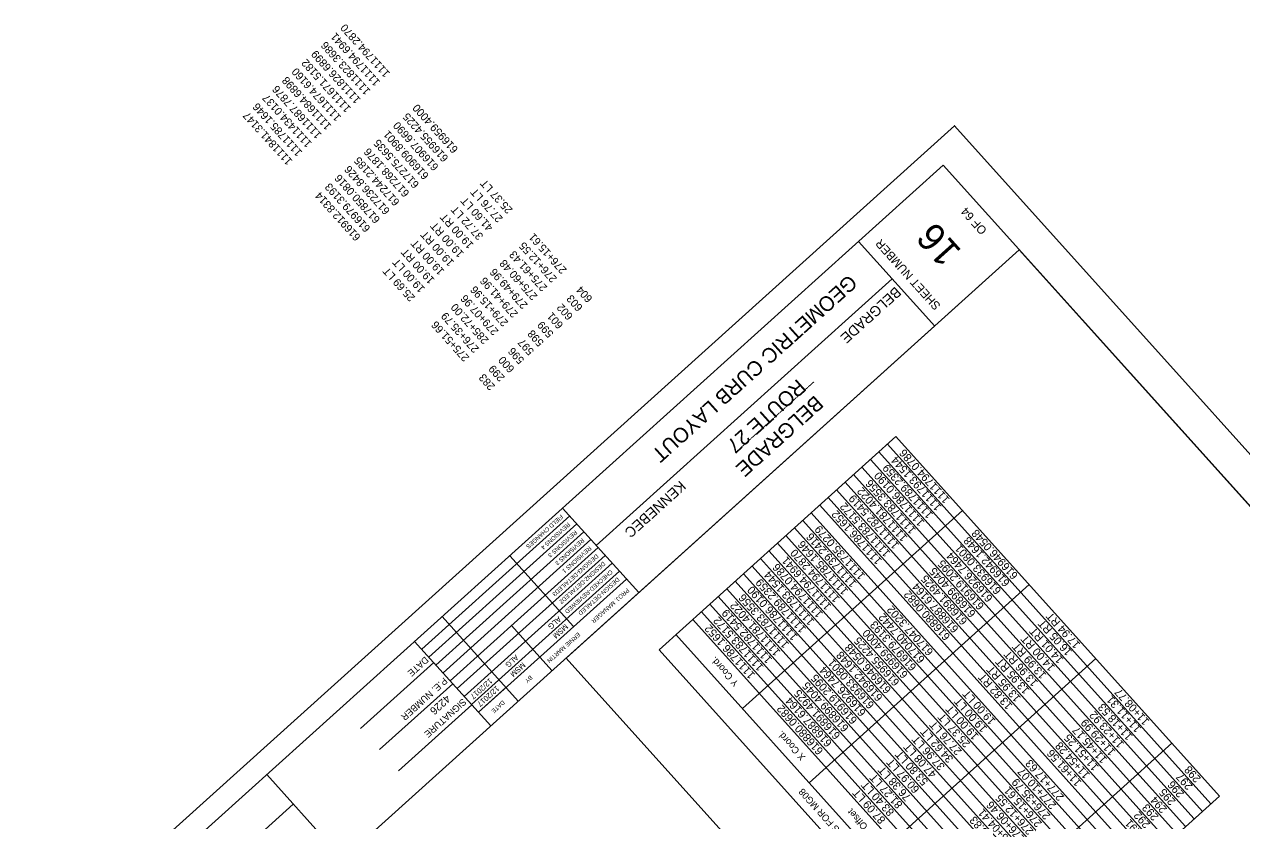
# Model space of a CAD drawing. Extents: x 1111534 to 1112511, y 616515 to 617559.
# Drawn here: x 1111534 to 1112068, y 617209 to 617559 of the extents above; entities that cross this region are included whole.
import ezdxf

# ---------------------------------------------------------------- set-up
doc = ezdxf.new("R2010")
doc.units = 0
for name, color, linetype in [('ANNOTATION', 7, 'Continuous'), ('BORDER', 7, 'Continuous'), ('BRIDGE_TITLE', 7, 'Continuous'), ('CLIPS', 7, 'Continuous'), ('H_V CONTROLS', 7, 'Continuous'), ('HIGHWAY_TITLE', 7, 'Continuous'), ('PLOT BOUNDARY', 7, 'Continuous')]:
    doc.layers.add(name, color=color, linetype=linetype)

msp = doc.modelspace()

# ---------------------------------------------------------------- linework, layer by layer
at = {"layer": 'BORDER'}
for p, q in [((1111937.23, 617496.95), (1111547.08, 617145.66)), ((1112472.55, 616902.44), (1111937.25, 617496.96)), ((1111970.69, 617459.79), (1111580.54, 617108.5)), ((1111933.53, 617426.34), (1111900.08, 617463.49)), ((1111914.83, 617447.11), (1111784.78, 617330.01)), ((1111803.48, 617309.24), (1111770.03, 617346.39)), ((1111738.46, 617250.69), (1111705, 617287.85)), ((1111713.37, 617278.56), (1111681.23, 617249.63)), ((1111721.73, 617269.27), (1111689.6, 617240.34)), ((1111730.09, 617259.98), (1111697.96, 617231.05)), ((1111673.46, 617192.17), (1111640.01, 617229.33)), ((1111651.63, 617216.4), (1111558.74, 617132.76))]:
    msp.add_line(p, q, dxfattribs=at)
for points in [[(1111773.13, 617342.93), (1111708.12, 617284.39)], [(1111776.25, 617339.46), (1111711.23, 617280.93)], [(1111779.36, 617336), (1111714.35, 617277.46)], [(1111782.48, 617332.54), (1111717.47, 617274)], [(1111785.6, 617329.08), (1111720.58, 617270.54)], [(1111788.72, 617325.62), (1111723.7, 617267.08)], [(1111726.82, 617263.62), (1111791.83, 617322.16)], [(1111774.86, 617294.33), (1111746.8, 617325.48)], [(1111794.95, 617318.69), (1111729.94, 617260.15)], [(1111798.07, 617315.23), (1111735.68, 617259.05)], [(1111750.53, 617261.56), (1111717.08, 617298.72)], [(1111759.99, 617280.95), (1111747.53, 617294.79)], [(1111765.4, 617274.94), (1111759.99, 617280.95)], [(1111745.13, 617267.56), (1111733.06, 617256.69)]]:
    msp.add_lwpolyline(points, dxfattribs=at)
at = {"layer": 'CLIPS'}
msp.add_lwpolyline([(1112472.55, 616902.44), (1111970.7, 617459.8), (1111771.54, 617280.48), (1112273.39, 616723.12)], close=True, dxfattribs=at)
at = {"layer": 'H_V CONTROLS'}
for p, q in [((1111812.4, 617284.13), (1111916.44, 617377.81)), ((1112054.91, 617216.54), (1111912.72, 617374.46)), ((1112058.63, 617219.89), (1111916.44, 617377.81)), ((1112051.2, 617213.2), (1111909.01, 617371.11)), ((1112043.76, 617206.51), (1111901.57, 617364.42)), ((1112047.48, 617209.85), (1111905.29, 617367.77)), ((1112036.33, 617199.81), (1111894.14, 617357.73)), ((1112040.05, 617203.16), (1111897.86, 617361.08)), ((1112032.62, 617196.47), (1111890.43, 617354.39)), ((1112025.19, 617189.78), (1111883, 617347.7)), ((1112028.9, 617193.12), (1111886.71, 617351.04)), ((1111849.1, 617258.31), (1111945.71, 617345.29)), ((1112021.47, 617186.43), (1111879.28, 617344.35)), ((1112014.04, 617179.74), (1111871.85, 617337.66)), ((1112017.75, 617183.09), (1111875.56, 617341)), ((1112010.32, 617176.39), (1111868.13, 617334.31)), ((1112002.89, 617169.7), (1111860.7, 617327.62)), ((1112006.61, 617173.05), (1111864.42, 617330.97)), ((1111995.46, 617163.01), (1111853.27, 617320.93)), ((1111999.18, 617166.36), (1111856.99, 617324.28)), ((1111991.74, 617159.67), (1111849.55, 617317.58)), ((1111984.31, 617152.97), (1111842.12, 617310.89)), ((1111988.03, 617156.32), (1111845.84, 617314.24)), ((1111878.38, 617225.79), (1111974.99, 617312.78)), ((1111980.6, 617149.63), (1111838.41, 617307.55)), ((1111973.17, 617142.94), (1111830.98, 617300.86)), ((1111976.88, 617146.28), (1111834.69, 617304.2)), ((1111969.45, 617139.59), (1111827.26, 617297.51)), ((1111962.02, 617132.9), (1111819.83, 617290.82)), ((1111954.59, 617126.21), (1111812.4, 617284.13)), ((1111907.65, 617193.28), (1112004.26, 617280.27)), ((1111941.11, 617156.12), (1112037.72, 617243.11)), ((1111954.59, 617126.21), (1112058.63, 617219.89))]:
    msp.add_line(p, q, dxfattribs=at)
at = {"layer": 'PLOT BOUNDARY'}
msp.add_lwpolyline([(1112510.99, 616882.61), (1111942.23, 617514.28), (1111533.5, 617146.26), (1112102.26, 616514.59)], close=True, dxfattribs=at)

# ---------------------------------------------------------------- texts
at = {"layer": 'ANNOTATION'}
for s, height, rotation, p in [('1111794.2870', 3.45, 132, (1111694.36, 617537.42)), ('1111823.3686', 3.45, 132, (1111685.8, 617529.71)), ('1111794.6941', 3.45, 132, (1111690.08, 617533.57)), ('1111826.6899', 3.45, 132, (1111681.52, 617525.86)), ('1111671.5182', 3.45, 132, (1111677.24, 617522)), ('1111684.6898', 3.45, 132, (1111668.68, 617514.29)), ('1111674.6160', 3.45, 132, (1111672.96, 617518.14)), ('1111687.7876', 3.45, 132, (1111664.39, 617510.43)), ('1111785.1646', 3.45, 132, (1111655.83, 617502.72)), ('1111434.0137', 3.45, 132, (1111660.11, 617506.58)), ('616959.4000', 3.45, 132, (1111724.35, 617504.12)), ('1111841.3147', 3.45, 132, (1111651.55, 617498.87)), ('616955.4225', 3.45, 132, (1111720.07, 617500.26)), ('616907.6690', 3.45, 132, (1111715.79, 617496.41)), ('617275.5635', 3.45, 132, (1111707.22, 617488.7)), ('616909.8901', 3.45, 132, (1111711.5, 617492.55)), ('617268.1876', 3.45, 132, (1111702.94, 617484.84)), ('617244.2185', 3.45, 132, (1111698.66, 617480.99)), ('617850.0816', 3.45, 132, (1111690.1, 617473.28)), ('617236.8426', 3.45, 132, (1111694.38, 617477.13)), ('616979.3193', 3.45, 132, (1111685.81, 617469.42)), ('27.76 LT', 3.45, 132, (1111744, 617473.69)), ('25.37 LT', 3.45, 132, (1111748.28, 617477.54)), ('616912.8314', 3.45, 132, (1111681.53, 617465.57)), ('41.60 LT', 3.45, 132, (1111739.71, 617469.83)), ('37.72 LT', 3.45, 132, (1111735.43, 617465.98)), ('19.00 RT', 3.45, 132, (1111726.87, 617458.27)), ('19.00 RT', 3.45, 132, (1111731.15, 617462.12)), ('19.00 RT', 3.45, 132, (1111722.59, 617454.41)), ('276+15.61', 3.45, 132, (1111772.06, 617451.13)), ('19.00 RT', 3.45, 132, (1111714.02, 617446.7)), ('19.00 RT', 3.45, 132, (1111718.31, 617450.56)), ('276+12.55', 3.45, 132, (1111767.78, 617447.28)), ('19.00 LT', 3.45, 132, (1111709.74, 617442.85)), ('275+60.48', 3.45, 132, (1111759.21, 617439.57)), ('275+61.43', 3.45, 132, (1111763.5, 617443.42)), ('25.69 LT', 3.45, 132, (1111705.46, 617438.99)), ('279+49.96', 3.45, 132, (1111754.93, 617435.71)), ('279+15.96', 3.45, 132, (1111746.37, 617428)), ('279+41.96', 3.45, 132, (1111750.65, 617431.86)), ('604', 3.45, 132, (1111783.41, 617438.53)), ('279+07.96', 3.45, 132, (1111742.09, 617424.15)), ('603', 3.45, 132, (1111779.13, 617434.67)), ('285+72.00', 3.45, 132, (1111737.81, 617420.29)), ('602', 3.45, 132, (1111774.84, 617430.82)), ('275+51.66', 3.45, 132, (1111729.24, 617412.58)), ('276+35.79', 3.45, 132, (1111733.52, 617416.44)), ('599', 3.45, 132, (1111766.28, 617423.11)), ('601', 3.45, 132, (1111770.56, 617426.96)), ('598', 3.45, 132, (1111762, 617419.25)), ('596', 3.45, 132, (1111753.44, 617411.54)), ('597', 3.45, 132, (1111757.72, 617415.4)), ('600', 3.45, 132, (1111749.15, 617407.69)), ('299', 3.45, 132, (1111744.87, 617403.83)), ('283', 3.45, 132, (1111740.59, 617399.98)), ('1111793.1544', 3.5156, 132, (1111936.79, 617347.07)), ('1111794.0786', 3.5156, 132, (1111940.37, 617350.29)), ('1111789.2359', 3.5156, 132, (1111933.02, 617343.68)), ('1111783.3556', 3.5156, 132, (1111925.49, 617336.89)), ('1111786.0190', 3.5156, 132, (1111929.27, 617340.3)), ('1111781.4022', 3.5156, 132, (1111921.8, 617333.57)), ('1111783.5172', 3.5156, 132, (1111914.27, 617326.79)), ('1111782.5419', 3.5156, 132, (1111918.13, 617330.27)), ('1111786.1652', 3.5156, 132, (1111910.58, 617323.47)), ('1111735.0279', 3.5156, 132, (1111903.15, 617316.78)), ('616946.0548', 3.5156, 132, (1111970.37, 617316.97)), ('1111785.1646', 3.5156, 132, (1111895.75, 617310.11)), ('1111739.2416', 3.5156, 132, (1111899.47, 617313.46)), ('616942.1648', 3.5156, 132, (1111966.79, 617313.75)), ('1111794.2870', 3.45, 132, (1111892.04, 617306.77)), ('616926.7464', 3.5156, 132, (1111959.27, 617306.98)), ('616933.0801', 3.5156, 132, (1111963.02, 617310.36)), ('1111794.0786', 3.5156, 132, (1111884.63, 617300.1)), ('1111794.6941', 3.45, 132, (1111888.31, 617303.42)), ('616919.2095', 3.5156, 132, (1111955.49, 617303.57)), ('1111789.2359', 3.5156, 132, (1111877.22, 617293.43)), ('1111793.1544', 3.5156, 132, (1111880.91, 617296.75)), ('616891.4925', 3.5156, 132, (1111948.13, 617296.95)), ('616899.4045', 3.5156, 132, (1111951.8, 617300.26)), ('1111786.0190', 3.5156, 132, (1111873.54, 617290.11)), ('616880.0682', 3.5156, 132, (1111940.58, 617290.15)), ('616887.6164', 3.5156, 132, (1111944.27, 617293.48)), ('1111781.4022', 3.5156, 132, (1111866, 617283.33)), ('1111783.3556', 3.5156, 132, (1111869.75, 617286.71)), ('1111782.5419', 3.5156, 132, (1111862.32, 617280.01)), ('617040.7442', 3.5156, 132, (1111929.47, 617280.14)), ('617047.3202', 3.5156, 132, (1111933.15, 617283.46)), ('17.94 RT', 3.516, 132, (1111997.71, 617286.61)), ('1111786.1652', 3.5156, 132, (1111854.81, 617273.25)), ('1111783.5172', 3.5156, 132, (1111858.63, 617276.69)), ('616979.3193', 3.5156, 132, (1111925.75, 617276.8)), ('16.05 RT', 3.516, 132, (1111994.13, 617283.39)), ('616955.4225', 3.45, 132, (1111918.3, 617270.12)), ('616959.4000', 3.45, 132, (1111922.02, 617273.47)), ('14.00 RT', 3.516, 132, (1111986.61, 617276.62)), ('14.01 RT', 3.516, 132, (1111990.36, 617280)), ('616942.1648', 3.5156, 132, (1111910.91, 617263.43)), ('616946.0548', 3.5156, 132, (1111914.62, 617266.78)), ('13.96 RT', 3.516, 132, (1111979.14, 617269.89)), ('13.99 RT', 3.516, 132, (1111982.82, 617273.21)), ('616933.0801', 3.5156, 132, (1111907.22, 617260.12)), ('13.95 RT', 3.516, 132, (1111975.47, 617266.59)), ('616919.2095', 3.5156, 132, (1111899.75, 617253.39)), ('616926.7464', 3.5156, 132, (1111903.54, 617256.8)), ('13.82 RT', 3.516, 132, (1111967.92, 617259.79)), ('13.95 RT', 3.516, 132, (1111971.61, 617263.12)), ('616899.4045', 3.5156, 132, (1111896, 617250.01)), ('4226', 3.396, 222, (1111718.9, 617264.57)), ('616887.6164', 3.5156, 132, (1111888.63, 617243.38)), ('616891.4925', 3.5156, 132, (1111892.31, 617246.69)), ('19.00 LT', 3.516, 132, (1111956.8, 617249.78)), ('19.00 LT', 3.516, 132, (1111960.49, 617253.1)), ('11+11.31', 3.516, 132, (1112024.5, 617249.66)), ('11+08.77', 3.516, 132, (1112028.08, 617252.88)), ('616880.0682', 3.5156, 132, (1111884.81, 617239.94)), ('19.00 LT', 3.516, 132, (1111953.08, 617246.43)), ('11+23.92', 3.516, 132, (1112016.98, 617242.89)), ('11+18.53', 3.516, 132, (1112020.73, 617246.27)), ('27.76 LT', 3.45, 132, (1111945.65, 617239.74)), ('25.37 LT', 3.45, 132, (1111949.38, 617243.09)), ('11+29.99', 3.516, 132, (1112013.2, 617239.48)), ('37.96 LT', 3.516, 132, (1111938.24, 617233.07)), ('34.62 LT', 3.516, 132, (1111941.96, 617236.42)), ('11+51.25', 3.516, 132, (1112005.84, 617232.86)), ('11+45.17', 3.516, 132, (1112009.51, 617236.16)), ('47.08 LT', 3.516, 132, (1111934.56, 617229.75)), ('11+61.56', 3.516, 132, (1111998.29, 617226.06)), ('11+54.28', 3.516, 132, (1112001.98, 617229.38)), ('60.97 LT', 3.516, 132, (1111927.09, 617223.03)), ('53.80 LT', 3.516, 132, (1111930.87, 617226.44)), ('277+17.63', 3.516, 132, (1111990.59, 617219.68)), ('76.38 LT', 3.516, 132, (1111923.34, 617219.65)), ('277+10.07', 3.516, 132, (1111987.18, 617216.05)), ('298', 3.516, 132, (1112050.73, 617227.72)), ('83.40 LT', 3.516, 132, (1111915.97, 617213.01)), ('81.27 LT', 3.516, 132, (1111919.65, 617216.33)), ('276+15.61', 3.45, 132, (1111980.89, 617208.1)), ('276+35.79', 3.516, 132, (1111984.6, 617211.44)), ('296', 3.516, 132, (1112043.38, 617221.11)), ('297', 3.516, 132, (1112047.15, 617224.5)), ('87.09 LT', 3.516, 132, (1111912.15, 617209.58)), ('276+12.55', 3.45, 132, (1111977.16, 617204.74)), ('294', 3.516, 132, (1112035.85, 617214.32)), ('295', 3.516, 132, (1112039.63, 617217.73)), ('276+04.41', 3.516, 132, (1111969.76, 617198.08)), ('276+06.46', 3.516, 132, (1111973.47, 617201.42)), ('292', 3.516, 132, (1112028.49, 617207.7)), ('293', 3.516, 132, (1112032.16, 617211)), ('276+00.83', 3.516, 132, (1111966.07, 617194.76)), ('291', 3.516, 132, (1112024.63, 617204.23))]:
    msp.add_text(s, height=height, rotation=rotation, dxfattribs=at).set_placement(p)
at = {"layer": 'BORDER'}
for s, height, rotation, p in [('OF 64', 3.726, 132, (1111956.71, 617468.52)), ('16', 12.097, 132, (1111945.7, 617459.3)), ('SHEET NUMBER', 3.7264, 132, (1111936.38, 617435.4)), ('GEOMETRIC CURB LAYOUT', 6.5214, 222, (1111895.79, 617449.31)), ('FIELD CHANGES', 1.8637, 222, (1111769.21, 617343.66)), ('REVISIONS 4', 1.8637, 222, (1111772.33, 617340.2)), ('REVISIONS 3', 1.8637, 222, (1111775.44, 617336.73)), ('REVISIONS 2', 1.8637, 222, (1111778.56, 617333.27)), ('DESIGN3-DETAILED3', 1.8637, 222, (1111784.79, 617326.35)), ('REVISIONS 1', 1.8637, 222, (1111781.68, 617329.81)), ('DESIGN2-DETAILED2', 1.8637, 222, (1111787.79, 617323.03)), ('CHECKED-REVIEWED', 1.8637, 222, (1111791.03, 617319.42)), ('DESIGN-DETAILED', 1.8637, 222, (1111794.02, 617316.1)), ('PROJ. MANAGER', 1.8637, 222, (1111798.31, 617311.34)), ('ALG', 2.423, 222, (1111768.11, 617299.03)), ('MSM', 2.423, 222, (1111771.1, 617295.71)), ('ERNIE MARTIN', 1.8637, 222, (1111776.75, 617291.92)), ('DATE', 2.953, 222, (1111709.5, 617281.41)), ('ALG', 2.423, 222, (1111749.37, 617282.16)), ('MSM', 2.423, 222, (1111752.37, 617278.84)), ('BY', 1.857, 222, (1111755.78, 617273.04)), ('P.E. NUMBER', 2.9528, 222, (1111717.8, 617272.19)), ('12/2017', 2.423, 222, (1111737.92, 617271.85)), ('12/2017', 2.423, 222, (1111740.91, 617268.53)), ('SIGNATURE', 2.953, 222, (1111726.1, 617262.98)), ('DATE', 1.857, 222, (1111743.62, 617262.1))]:
    msp.add_text(s, height=height, rotation=rotation, dxfattribs=at).set_placement(p)
at = {"layer": 'BRIDGE_TITLE'}
for s, height, p in [('BELGRADE', 4.536, (1111916.25, 617443.88)), ('_____________', 4.5358, (1111881.11, 617400.95)), ('KENNEBEC', 4.536, (1111821.63, 617358.68))]:
    msp.add_text(s, height=height, rotation=222, dxfattribs=at).set_placement(p)
at = {"layer": 'H_V CONTROLS'}
for s, p in [('Y Coord.', (1111847.63, 617269.65)), ('X Coord.', (1111876.91, 617237.14)), ('CONTROL POINTS FOR MG08', (1111914.01, 617180.99)), ('Offset', (1111904.3, 617206.72))]:
    msp.add_text(s, height=3, rotation=132, dxfattribs=at).set_placement(p)
at = {"layer": 'HIGHWAY_TITLE'}
for s, p in [('ROUTE 27', (1111873.24, 617403.4)), ('BELGRADE', (1111880.88, 617396.23))]:
    msp.add_text(s, height=6.521, rotation=222, dxfattribs=at).set_placement(p)

doc.saveas('drawing.dxf')
